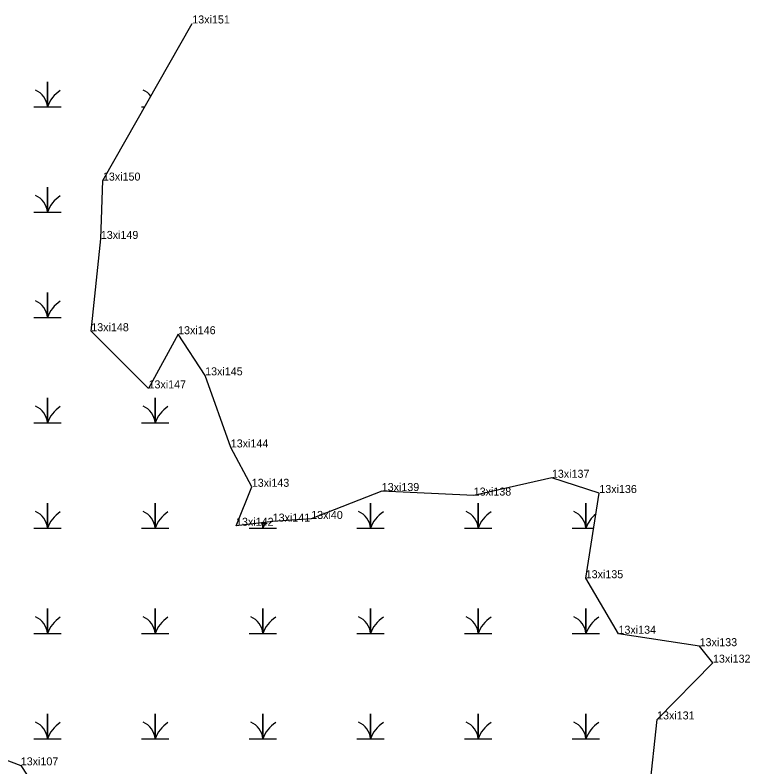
# Model space of a CAD drawing. Extents: x 2072529 to 2268796, y 436423 to 470397.
# Drawn here: x 2249753.4 to 2250212.3, y 445925.1 to 446394.8 of the extents above; entities that cross this region are included whole.
import ezdxf

# ---------------------------------------------------------------- set-up
doc = ezdxf.new("R2010")
doc.units = 0
for name, color, linetype in [('Exist Environmental Wetland Boundary', 7, 'Continuous'), ('Exist Environmental Wetland Boundary Cogo Comment', 7, 'Continuous'), ('Exist Environmental Wetland Boundary Cogo Point CELL', 7, 'Continuous'), ('Exist Hydro Swamp or Marsh', 7, 'Continuous')]:
    doc.layers.add(name, color=color, linetype=linetype)

msp = doc.modelspace()

# ---------------------------------------------------------------- linework, layer by layer
at = {"layer": 'Exist Environmental Wetland Boundary'}
for points in [[(2249836.74, 446161.55), (2249800.99, 446197.28), (2249806.95, 446254.92), (2249808.26, 446291.37), (2249864.05, 446389.51)], [(2250149.58, 445910.13), (2250154.33, 445954.77), (2250189.24, 445990.21), (2250180.89, 446000.53), (2250130.23, 446008.3), (2250109.76, 446042.98), (2250118.26, 446096.2), (2250088.64, 446105.72), (2250039.82, 446094.6), (2249982.38, 446097.44), (2249938.33, 446080.02), (2249914.27, 446078.35), (2249891.37, 446075.75), (2249901.21, 446100.09), (2249888.11, 446124.67), (2249872.1, 446169.71), (2249855.21, 446195.4), (2249836.74, 446161.55)], [(2249726.67, 445937.54), (2249756.96, 445926.08), (2249776.43, 445896.46)]]:
    msp.add_lwpolyline(points, dxfattribs=at)
at = {"layer": 'Exist Environmental Wetland Boundary Cogo Point CELL'}
for p, q in [((2249864.05, 446389.51), (2249864.05, 446389.51)), ((2249808.26, 446291.37), (2249808.26, 446291.37)), ((2249806.95, 446254.92), (2249806.95, 446254.92)), ((2249800.99, 446197.28), (2249800.99, 446197.28)), ((2249855.21, 446195.4), (2249855.21, 446195.4)), ((2249872.1, 446169.71), (2249872.1, 446169.71)), ((2249836.74, 446161.55), (2249836.74, 446161.55)), ((2249888.11, 446124.67), (2249888.11, 446124.67)), ((2250088.64, 446105.72), (2250088.64, 446105.72)), ((2249901.21, 446100.09), (2249901.21, 446100.09)), ((2249982.38, 446097.44), (2249982.38, 446097.44)), ((2250118.26, 446096.2), (2250118.26, 446096.2)), ((2250039.82, 446094.6), (2250039.82, 446094.6)), ((2249914.27, 446078.35), (2249914.27, 446078.35)), ((2249938.33, 446080.02), (2249938.33, 446080.02)), ((2249891.37, 446075.75), (2249891.37, 446075.75)), ((2250109.76, 446042.98), (2250109.76, 446042.98)), ((2250130.23, 446008.3), (2250130.23, 446008.3)), ((2250180.89, 446000.53), (2250180.89, 446000.53)), ((2250189.24, 445990.21), (2250189.24, 445990.21)), ((2250154.33, 445954.77), (2250154.33, 445954.77)), ((2249756.96, 445926.08), (2249756.96, 445926.08))]:
    msp.add_line(p, q, dxfattribs=at)
at = {"layer": 'Exist Hydro Swamp or Marsh'}
for points in [[(2249765.01, 446337.37), (2249773.61, 446337.37), (2249773.61, 446353.15), (2249773.61, 446337.37), (2249782.22, 446337.37)], [(2249832.26, 446337.37), (2249834.41, 446337.37)], [(2249765.01, 446271.57), (2249773.61, 446271.57), (2249773.61, 446287.35), (2249773.61, 446271.57), (2249782.22, 446271.57)], [(2249765.01, 446205.77), (2249773.61, 446205.77), (2249773.61, 446221.55), (2249773.61, 446205.77), (2249782.22, 446205.77)], [(2249765.01, 446139.97), (2249773.61, 446139.97), (2249773.61, 446155.75), (2249773.61, 446139.97), (2249782.22, 446139.97)], [(2249832.26, 446139.97), (2249840.86, 446139.97), (2249840.86, 446155.75), (2249840.86, 446139.97), (2249849.47, 446139.97)], [(2249765.01, 446074.17), (2249773.61, 446074.17), (2249773.61, 446089.95), (2249773.61, 446074.17), (2249782.22, 446074.17)], [(2249832.26, 446074.17), (2249840.86, 446074.17), (2249840.86, 446089.95), (2249840.86, 446074.17), (2249849.47, 446074.17)], [(2249966.76, 446074.17), (2249975.36, 446074.17), (2249975.36, 446089.95), (2249975.36, 446074.17), (2249983.97, 446074.17)], [(2250034.01, 446074.17), (2250042.61, 446074.17), (2250042.61, 446089.95), (2250042.61, 446074.17), (2250051.22, 446074.17)], [(2250101.26, 446074.17), (2250109.86, 446074.17), (2250109.86, 446089.95), (2250109.86, 446074.17), (2250114.74, 446074.17)], [(2249899.51, 446074.17), (2249908.11, 446074.17), (2249908.11, 446077.65)], [(2249908.11, 446077.65), (2249908.11, 446074.17), (2249916.72, 446074.17)], [(2249765.01, 446008.37), (2249773.61, 446008.37), (2249773.61, 446024.15), (2249773.61, 446008.37), (2249782.22, 446008.37)], [(2249832.26, 446008.37), (2249840.86, 446008.37), (2249840.86, 446024.15), (2249840.86, 446008.37), (2249849.47, 446008.37)], [(2249899.51, 446008.37), (2249908.11, 446008.37), (2249908.11, 446024.15), (2249908.11, 446008.37), (2249916.72, 446008.37)], [(2249966.76, 446008.37), (2249975.36, 446008.37), (2249975.36, 446024.15), (2249975.36, 446008.37), (2249983.97, 446008.37)], [(2250034.01, 446008.37), (2250042.61, 446008.37), (2250042.61, 446024.15), (2250042.61, 446008.37), (2250051.22, 446008.37)], [(2250101.26, 446008.37), (2250109.86, 446008.37), (2250109.86, 446024.15), (2250109.86, 446008.37), (2250118.47, 446008.37)], [(2249765.01, 445942.57), (2249773.61, 445942.57), (2249773.61, 445958.35), (2249773.61, 445942.57), (2249782.22, 445942.57)], [(2249832.26, 445942.57), (2249840.86, 445942.57), (2249840.86, 445958.35), (2249840.86, 445942.57), (2249849.47, 445942.57)], [(2249899.51, 445942.57), (2249908.11, 445942.57), (2249908.11, 445958.35), (2249908.11, 445942.57), (2249916.72, 445942.57)], [(2249966.76, 445942.57), (2249975.36, 445942.57), (2249975.36, 445958.35), (2249975.36, 445942.57), (2249983.97, 445942.57)], [(2250034.01, 445942.57), (2250042.61, 445942.57), (2250042.61, 445958.35), (2250042.61, 445942.57), (2250051.22, 445942.57)], [(2250101.26, 445942.57), (2250109.86, 445942.57), (2250109.86, 445958.35), (2250109.86, 445942.57), (2250118.47, 445942.57)]]:
    msp.add_lwpolyline(points, dxfattribs=at)
for centre, radius, start, end in [((2249761.35, 446336.48), 12.3, 4.1403, 67.535), ((2249791.86, 446331.3), 19.22, 122.1274, 161.6222), ((2249828.6, 446336.48), 12.3, 38.3438, 67.535), ((2249761.35, 446270.68), 12.3, 4.1403, 67.535), ((2249791.86, 446265.5), 19.22, 122.1274, 161.6222), ((2249761.35, 446204.88), 12.3, 4.1403, 67.535), ((2249791.86, 446199.7), 19.22, 122.1274, 161.6222), ((2249761.35, 446139.08), 12.3, 4.1403, 67.535), ((2249791.86, 446133.9), 19.22, 122.1274, 161.6222), ((2249828.6, 446139.08), 12.3, 4.1403, 67.535), ((2249859.11, 446133.9), 19.22, 122.1274, 161.6222), ((2249761.35, 446073.28), 12.3, 4.1403, 67.535), ((2249791.86, 446068.1), 19.22, 122.1274, 161.6222), ((2249828.6, 446073.28), 12.3, 4.1403, 67.535), ((2249859.11, 446068.1), 19.22, 122.1274, 161.6222), ((2249963.1, 446073.28), 12.3, 4.1403, 67.535), ((2249993.61, 446068.1), 19.22, 122.1274, 161.6222), ((2250030.35, 446073.28), 12.3, 4.1403, 67.535), ((2250060.86, 446068.1), 19.22, 122.1274, 161.6222), ((2250097.6, 446073.28), 12.3, 4.1403, 67.535), ((2250128.11, 446068.1), 19.22, 128.3491, 161.6222), ((2249895.85, 446073.28), 12.3, 4.1403, 20.4214), ((2249926.36, 446068.1), 19.22, 149.5658, 161.6222), ((2249761.35, 446007.48), 12.3, 4.1403, 67.535), ((2249791.86, 446002.3), 19.22, 122.1274, 161.6222), ((2249828.6, 446007.48), 12.3, 4.1403, 67.535), ((2249859.11, 446002.3), 19.22, 122.1274, 161.6222), ((2249895.85, 446007.48), 12.3, 4.1403, 67.535), ((2249926.36, 446002.3), 19.22, 122.1274, 161.6222), ((2249963.1, 446007.48), 12.3, 4.1403, 67.535), ((2249993.61, 446002.3), 19.22, 122.1274, 161.6222), ((2250030.35, 446007.48), 12.3, 4.1403, 67.535), ((2250060.86, 446002.3), 19.22, 122.1274, 161.6222), ((2250097.6, 446007.48), 12.3, 4.1403, 67.535), ((2250128.11, 446002.3), 19.22, 122.1274, 161.6222), ((2249761.35, 445941.68), 12.3, 4.1403, 67.535), ((2249791.86, 445936.5), 19.22, 122.1274, 161.6222), ((2249828.6, 445941.68), 12.3, 4.1403, 67.535), ((2249859.11, 445936.5), 19.22, 122.1274, 161.6222), ((2249895.85, 445941.68), 12.3, 4.1403, 67.535), ((2249926.36, 445936.5), 19.22, 122.1274, 161.6222), ((2249963.1, 445941.68), 12.3, 4.1403, 67.535), ((2249993.61, 445936.5), 19.22, 122.1274, 161.6222), ((2250030.35, 445941.68), 12.3, 4.1403, 67.535), ((2250060.86, 445936.5), 19.22, 122.1274, 161.6222), ((2250097.6, 445941.68), 12.3, 4.1403, 67.535), ((2250128.11, 445936.5), 19.22, 122.1274, 161.6222)]:
    msp.add_arc(centre, radius, start, end, dxfattribs=at)

# ---------------------------------------------------------------- texts
at = {"layer": 'Exist Environmental Wetland Boundary Cogo Comment'}
for s, p in [('13xi151', (2249864.05, 446389.51)), ('13xi150', (2249808.26, 446291.37)), ('13xi149', (2249806.95, 446254.92)), ('13xi148', (2249800.99, 446197.28)), ('13xi146', (2249855.21, 446195.4)), ('13xi145', (2249872.1, 446169.71)), ('13xi147', (2249836.74, 446161.55)), ('13xi144', (2249888.11, 446124.67)), ('13xi137', (2250088.64, 446105.72)), ('13xi143', (2249901.21, 446100.09)), ('13xi139', (2249982.38, 446097.44)), ('13xi136', (2250118.26, 446096.2)), ('13xi138', (2250039.82, 446094.6)), ('13xi141', (2249914.27, 446078.35)), ('13xi40', (2249938.33, 446080.02)), ('13xi142', (2249891.37, 446075.75)), ('13xi135', (2250109.76, 446042.98)), ('13xi134', (2250130.23, 446008.3)), ('13xi133', (2250180.89, 446000.53)), ('13xi132', (2250189.24, 445990.21)), ('13xi131', (2250154.33, 445954.77)), ('13xi107', (2249756.96, 445926.08))]:
    msp.add_text(s, height=5, dxfattribs=at).set_placement(p)

doc.saveas('drawing.dxf')
